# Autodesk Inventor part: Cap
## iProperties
Shininess: 20.0
Length Units: 11269
Angle Units: 11279
Time Units: 11290
Mass Units: 11283
Length Display Precision: 3
Angle Display Precision: 2
Created: 2001-04
Part Number: Cap
Material: Standard
Document SubType Name: Modellieren
Designer: dl
Density: 0.0
Volumn: 0.0
Area: 0.0
PropertySet Name: Model Information
Control State: 0
Master: False
Checked Out: False
Author: dl
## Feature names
1. Revolution1
2. Fillet1
